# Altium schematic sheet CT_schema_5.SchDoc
size 244 x 277 mm
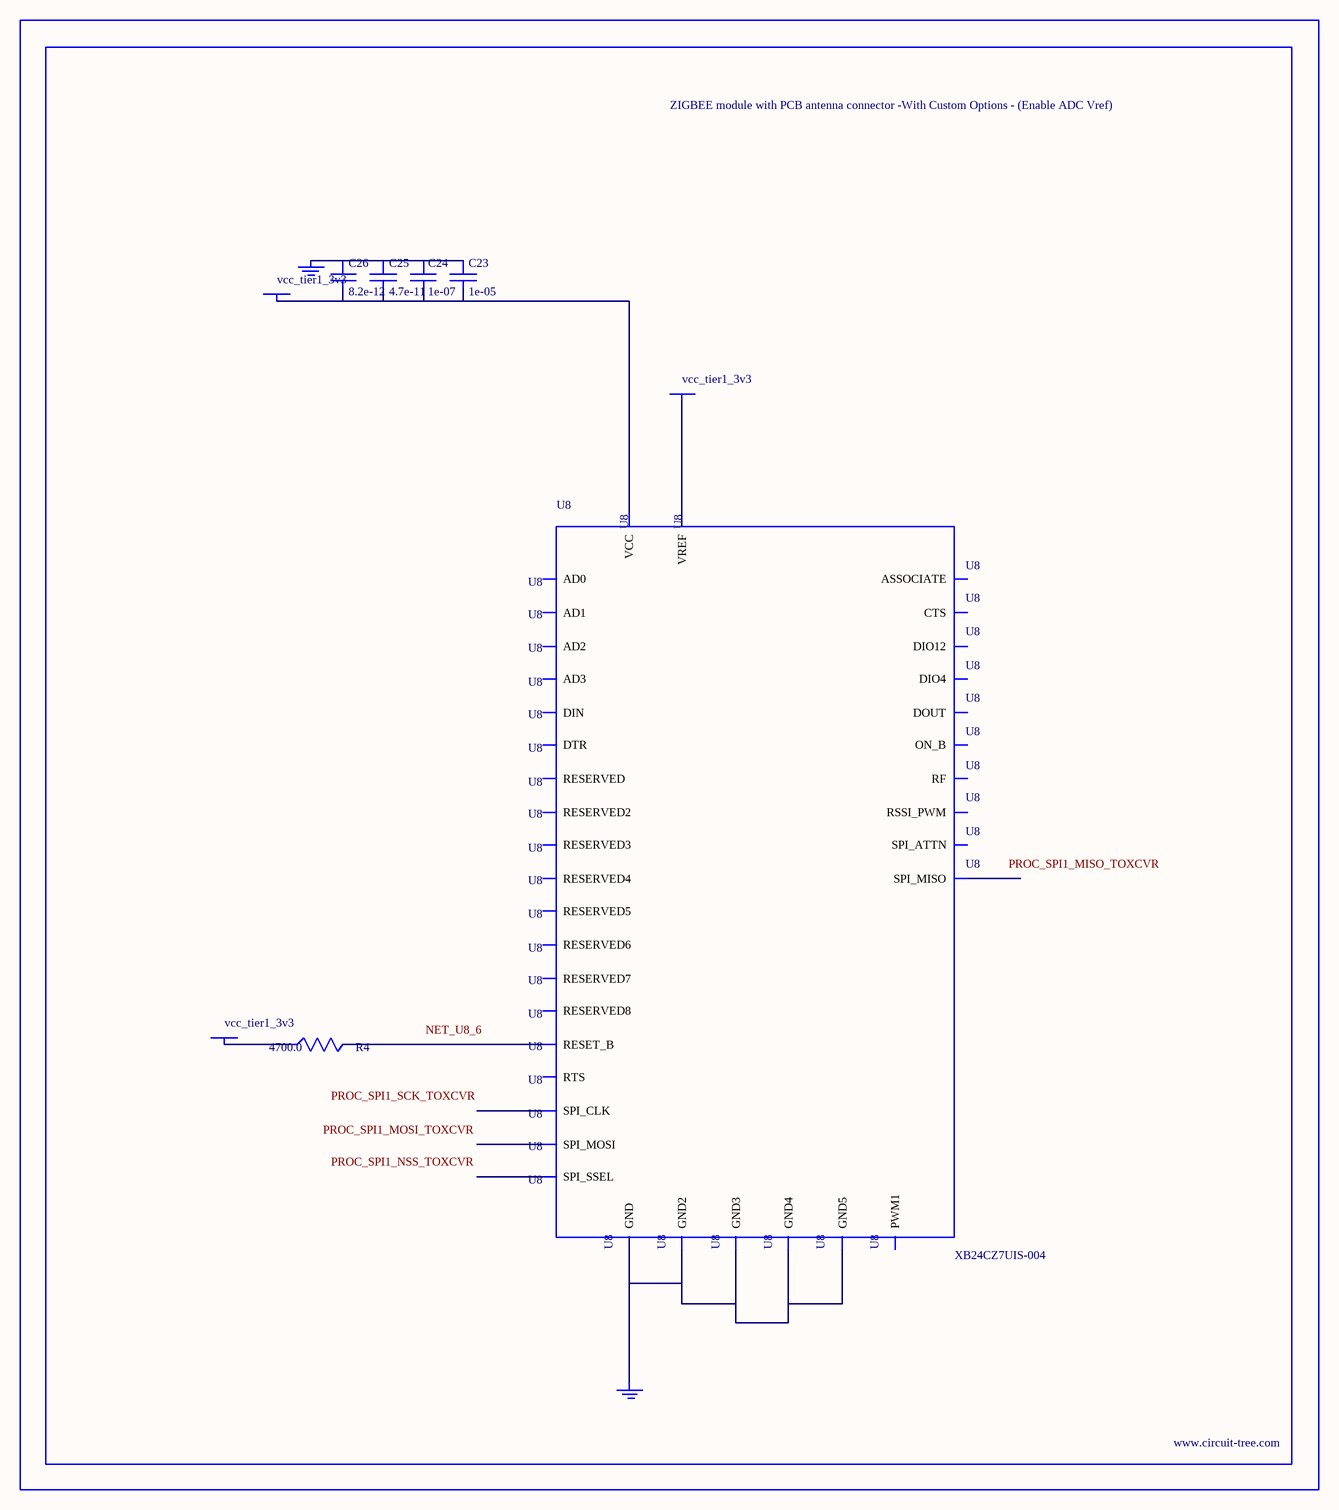
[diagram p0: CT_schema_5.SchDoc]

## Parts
BORDER4  (no value)
C23  1e-05  [C0805]
C24  1e-07  [C0402]
C25  4.7e-11  [C0402]
C26  8.2e-12  [C0603]
GND_INSTANCE_4_0  (no value)
GND_INSTANCE_4_1  (no value)
POWER_INSTANCE_4_0  vcc_tier1_3v3
POWER_INSTANCE_4_1  vcc_tier1_3v3
POWER_INSTANCE_4_2  vcc_tier1_3v3
R4  4700.0  [R0603]
U8  XB24CZ7UIS-004  [XB24CZ7UIS-004]

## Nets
NetC23_1: C23.1 C24.1 C25.1 C26.1 GND_INSTANCE_4_0.0(GND)
NetC23_2: C23.2 C24.2 C25.2 C26.2 POWER_INSTANCE_4_0.0(PWR) U8.2(VCC)
NetGND_INSTANCE_4_1_0: GND_INSTANCE_4_1.0(GND) U8.1(GND) U8.11(GND2) U8.13(GND3) U8.22(GND4) U8.35(GND5)
NetPOWER_INSTANCE_4_1_0: POWER_INSTANCE_4_1.0(PWR) R4.1
NetPOWER_INSTANCE_4_2_0: POWER_INSTANCE_4_2.0(PWR) U8.27(VREF)
NetR4_2: R4.2 U8.6(RESET_B)

Not connected (* = marked no-connect by the designer): U8 3(DOUT) 4(DIN) 5(DIO12) 7(RSSI_PWM) 8(PWM1) 9(RESERVED) 10(DTR) 12(SPI_ATTN) 14(SPI_CLK) 15(SPI_SSEL) 16(SPI_MOSI) 17(SPI_MISO) 18(RESERVED2) 19(RESERVED3) 20(RESERVED4) 21(RESERVED5) 23(RESERVED6) 24(DIO4) 25(CTS) 26(ON_B) 28(ASSOCIATE) 29(RTS) 30(AD3) 31(AD2) 32(AD1) 33(AD0) 34(RESERVED7) 36(RF) 37(RESERVED8)

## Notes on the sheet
- Labels drawn without touching a wire or pin: NET_U8_6, PROC_SPI1_MISO_TOXCVR, PROC_SPI1_MOSI_TOXCVR, PROC_SPI1_NSS_TOXCVR, PROC_SPI1_SCK_TOXCVR

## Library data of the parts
BORDER4 = BORDER_PAGE4
C23 = C0805C106K8RACTU
C24 = C0402C104K3RACTU
C25 = C0402C470K3RAC
C26 = 06035J8R2BBTTR
GND_INSTANCE_4_0 GND_INSTANCE_4_1 = GND
POWER_INSTANCE_4_0-POWER_INSTANCE_4_2 = PWR
R4 = RC0603JR-074K7L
